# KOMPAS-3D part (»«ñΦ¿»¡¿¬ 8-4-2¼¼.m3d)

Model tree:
1. Эскиз:12
2. Операция выдавливания:5
     Расстояние 1 = 2
3. Эскиз:13
4. Операция вращения:5
     Угол 1 = 360
5. Массив по концентрической сетке:3  (with: Операция вращения:5)  (labels: Экземпляр ( 1, 1 ); Экземпляр ( 1, 2 ); Экземпляр ( 1, 3 ); Экземпляр ( 1, 4 ))
     N 2 = 6; Шаг 2 = 360
6. Эскиз:14
7. Отверстие:5
8. Скругление:1
     Радиус = 0.1

Referenced files in C:\Program Files\ASCON\KOMPAS-3D V12\Sys\: holelib.lfr
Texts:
  подшипник 8
  подшипник 13х5х4
  Отверстие 01
  (вариант 1)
